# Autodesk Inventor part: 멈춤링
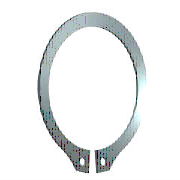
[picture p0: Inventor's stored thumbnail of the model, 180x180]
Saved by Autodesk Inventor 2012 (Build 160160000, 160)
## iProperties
Created: 2014-12
Part Number: 멈춤링
Material: 강, 연강
Description: 리테이닝 링(C형)
Document SubType Name: Modeling
Standard: KS B 1336
Designer: KYOUNG IL JANG
Standards Organization: KS
Language: ko-KR
Size Designation: 17 x 1
Categories: <MemberInstance><Categories><Category DisplayName="샤프트 부품" InternalName="7f7aeb1f-a693-4053-b835-cee3144e0d98" Mnemonic="SHFT"><Category DisplayName="써클립" Inter
Density: 7.86 g/cm^3
Mass: 0.979804 g
Surface Area: 3.83537 cm^2
Volume: 0.124657 cm^3
Company: 한국ATC센터
Author: KYOUNG IL JANG
IsCustomPart: 0
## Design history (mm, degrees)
sketch "스케치1"
  geometry: L1 (-6, 0)-(6, 0) reference; L2 (0, 20.189)-(0, -80.536) reference; L3 (-48.09, 0)-(48.09, 0) reference; L4 (-0.425, -16.589)-(-0.425, -20.289); L5 (-0.425, -6.54)-(-0.425, -13.29); L6 (-2.795, 2.2)-(3.672, 2.2); L7 (0.425, -6.54)-(0.425, -13.29); L8 (0.425, -16.589)-(0.425, -20.289); C1 r 0.85 at (-1.7, -18.452); C2 r 0.85 at (1.7, -18.452); A1 r 8.1 centre (0, -8.5) between (0.425, -16.589) and (-0.425, -16.589); A2 r 10.15 centre (0, -7.95) between (4.363, -17.114) and (-4.363, -17.114); A3 r 11.797 centre (0, -8.5) between (-1.986, -20.128) and (-0.425, -20.289); A4 r 1.7 centre (-1.7, -18.452) between (-3.397, -18.551) and (-1.986, -20.128); A5 r 1.7 centre (-5.094, -18.649) between (-3.397, -18.551) and (-4.363, -17.114); A6 r 1.7 centre (5.094, -18.649) between (4.363, -17.114) and (3.397, -18.551); A7 r 1.7 centre (1.7, -18.452) between (1.986, -20.128) and (3.397, -18.551); A8 r 11.797 centre (0, -8.5) between (0.425, -20.289) and (1.986, -20.128)
  constraints: 16 point on circle, 12 end point, 10 centre point, 9 symmetric about line, 5 point on line, 4 tangent, 3 coincident, 2 horizontal, 1 perpendicular, 1 vertical, 5 other
  dimensions: "d0" = 16.2 diameter of A1 (= ND); "d1" = 3.7 distance of L4.end L4.start (= SRB2); "d6" = 0.425 distance between parallel lines of L2 L5 (= 0.25 x SD5); "d7" = 2.2 distance between parallel lines of L6 L3 (= SRB1); "d8" = 0.55 distance of A1.centre A2.centre (= 0.25 x SRB1); "d9" = 1.7 radius of A4 (= SD5); "d10" = 1.7 radius of A5 (= SD5); "d11" = 1.275 distance from line of L4 A4.centre (= 0.75 x SD5); "d12" = 1.7 diameter of C1 (= SD5); "d13" = 1.7 diameter of C2 (= SD5); "d14" = 8.5 distance from line of A1.centre L1 (= 0.5 x WD)
extrude "본체" new body sketch "스케치1" distance "d2" = 1 (= SD); taper "d3" = 0 deg
workaxis "Work Axis1"
workplane "Work Plane1"
body "Solid1"
other parameters: "WD" = 17 (= WDMIN) [user parameter; used in 1 equation term], "SD" = 1 [user parameter; used in 1 equation term], "SRB1" = 2.2 [user parameter; used in 2 equation terms], "ND" = 16.2 [user parameter; used in 1 equation term], "SRB2" = 3.7 [user parameter; used in 1 equation term], "SD5" = 1.7 [user parameter; used in 6 equation terms], "d15" = 0, "d16" = 0, "d17" = 0, "d41" = 0, "d42" = 0, "WDMIN" = 17 [user parameter; used in 1 equation term], "SD3" = 15.7 [user parameter], "WDMAX" = 18 [user parameter]
